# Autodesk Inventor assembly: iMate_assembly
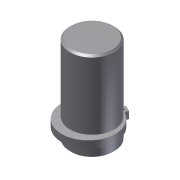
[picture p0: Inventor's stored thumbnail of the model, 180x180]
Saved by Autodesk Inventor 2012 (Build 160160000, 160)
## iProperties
Created: 2008-06
Part Number: iMate_assembly
Document SubType Name: Assembly
Designer: CADCIM
Author: CADCIM
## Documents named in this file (3)
- C:\Users\CadCim\Documents\SAILESH\inventor-2011-fact-prt\c17-inv-2011-prt\c17_inv_2012_prt\Tutorials\c17_tut02_inv_2012\iMate_assembly.iam
- C:\Users\CadCim\Documents\SAILESH\inventor-2011-fact-prt\c17-inv-2011-prt\Tutorials\c17-tut02-inv-2011\Shaft.ipt
- C:\Users\CadCim\Documents\SAILESH\inventor-2011-fact-prt\c17-inv-2011-prt\Tutorials\c17-tut02-inv-2011\circlip.ipt
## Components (2 placed, 2 different names)
1. Shaft:1
2. circlip:1
